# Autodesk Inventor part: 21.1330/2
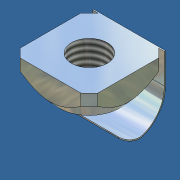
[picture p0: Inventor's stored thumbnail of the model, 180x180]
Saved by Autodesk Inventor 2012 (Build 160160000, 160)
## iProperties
Created: 2006-12
Part Number: 21.1330/2
Document SubType Name: Modeling
Designer: Andy Moles
Material: Steel, Mild
Density: 7.86 g/cm^3
Description: M6 SQUARE NUT POS FXG
Mass: 5.20508 g
Surface Area: 8.43697 cm^2
Volume: 0.662224 cm^3
Vendor: S
Title: M6 SQUARE NUT POS FXG
Author: Andy Moles
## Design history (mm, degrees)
sketch "Sketch2"
  geometry: L1 (-5.086, -6.5)-(5.086, -6.5); L2 (6.5, -5.086)-(6.5, 5.086); L3 (5.086, 6.5)-(-5.086, 6.5); L4 (-6.5, 5.086)-(-6.5, -5.086); L5 (-6.5, 6.5)-(6.5, -6.5); L6 (5.086, 6.5)-(6.5, 5.086); L7 (0, -6.5)-(0, 6.5); L8 (-6.5, 0)-(6.5, 0); L9 (-5.086, 6.5)-(-6.5, 5.086); L10 (-5.086, -6.5)-(-6.5, -5.086); L11 (5.086, -6.5)-(6.5, -5.086); C1 r 3 at (0, 0); 2 further points
  constraints: 22 end point, 6 symmetric about line, 4 parallel, 3 midpoint, 2 coincident, 2 perpendicular, 1 centre point, 1 horizontal
  dimensions: "THREAD" = 6 diameter of C1; "d3" = 45 deg angle of L3 L6 (derived); "d4" = 2 distance of L3.start L2.end
extrude "Extrusion1" new body sketch "Sketch2" distance "d5" = 5.5; taper "d6" = 0 deg
workplane "Work Plane1"
sketch "Sketch4"
  geometry: L1 (11.192, 0)-(5.192, 0) reference; L2 (8.192, 0)-(13.192, 0); L3 (16.385, 5.5)-(16.385, 3.5); L4 (13.192, 0)-(16.797, 3.952); L5 (13.192, 0)-(16.385, 0); L6 (16.385, 3.5)-(16.385, 0); L7 (16.797, 3.952)-(16.797, -0.412); L8 (16.797, -0.412)-(13.192, -0.412); L9 (13.192, -0.412)-(13.192, 0); L10 (8.192, 5.5)-(8.192, 0); L11 (16.385, 5.5)-(16.385, 0) reference; L12 (16.385, 3.5)-(17.502, 3.5); L13 (9.192, 5.5)-(16.385, 5.5) reference
  constraints: 20 end point, 6 perpendicular, 1 collinear, 1 midpoint, 1 parallel, 1 point on line
  dimensions: "d10" = 5 distance of L2.start L2.end; "d15" = 2 distance between parallel lines of L12 L13
revolve "Revolution1" sketch "Sketch4" stored, may be unused: angle "d12" = 90 deg
thread "Thread1" dims "d13" = 10, "d14" = 0
sketch "Sketch6"
  geometry: L1 (2.954, -2.535)-(2.954, 6.006); L2 (2.954, -2.535)-(2.954, -7.535); L3 (2.954, -2.535)-(3.154, -2.535); L4 (3.154, -2.535)-(3.154, -7.535); L5 (-2.646, -13.135)-(-2.646, -13.335); L6 (2.954, 0)-(2.954, -1.933); L7 (-8.632, -2.535)-(1.539, -2.535) reference; L8 (2.954, -2.535)-(2.954, -4.468) reference; A1 r 5.374 centre (-2.416, -7.766) between (-2.646, -13.135) and (2.954, -7.535); A2 r 5.574 centre (-2.416, -7.766) between (-2.646, -13.335) and (3.154, -7.535); 4 further points; 1 other entity
  constraints: 12 end point, 4 collinear, 4 point on circle, 2 centre point, 2 parallel, 2 perpendicular, 1 coincident, 1 horizontal, 3 other
  dimensions: "d25" = 5 distance of L1.start L2.end; "d23" = 0.2 distance of L1.start L3.end; "d22" = 0.2 distance of L5.start L5.end; "d21" = 10.8 distance from line of L5.end L3; "d24" = 5.37434 radius of A1
extrude "Extrusion3" join sketch "Sketch6" taper "d27" = 0 deg; stored distance "d28" = 12
fillet "Fillet2" dims "d29" = 2
body "Solid1"
